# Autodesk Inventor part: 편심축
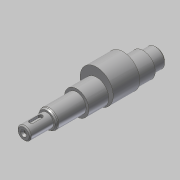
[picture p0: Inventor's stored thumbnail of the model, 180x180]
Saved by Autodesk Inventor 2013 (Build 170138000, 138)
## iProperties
Created: 2019-01
Part Number: 편심축
Material: 강철, 연강
Document SubType Name: Modeling
Designer: mduedu
Density: 7.86 g/cm^3
Mass: 326.79 g
Surface Area: 90.9817 cm^2
Volume: 41.5764 cm^3
Author: mduedu
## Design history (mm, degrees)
sketch "스케치1"
  geometry: L1 (0, 0)-(21, 0); L2 (21, 0)-(21, 6); L3 (21, 6)-(0, 6); L4 (0, 6)-(0, 0); L5 (21, 0)-(48, 0); L6 (48, 0)-(48, 8.5); L7 (48, 8.5)-(21, 8.5); L8 (21, 8.5)-(21, 0); L9 (48, 0)-(108, 0); L10 (108, 0)-(108, 11); L11 (108, 11)-(48, 11); L12 (48, 11)-(48, 0); L13 (108, 0)-(120, 0); L14 (120, 0)-(120, 8.5); L15 (120, 8.5)-(108, 8.5); L16 (108, 8.5)-(108, 0)
  constraints: 32 end point, 8 parallel, 4 horizontal, 4 perpendicular
  dimensions: "d0" = 120 distance between parallel lines of L14 L4; "d2" = 12 distance of L14.end L15.end; "d3" = 60 distance of L10.end L11.end; "d4" = 99 distance between parallel lines of L8 L14; "d5" = 12 diameter of L3 L1; "d6" = 17 diameter of L7 L5; "d7" = 17 diameter of L15 L13; "d8" = 22 diameter of L11 L9
revolve "회전1" sketch "스케치1" stored, may be unused: angle "d9" = 90 deg
node "작업 평면1"
sketch "스케치2"
  geometry: C1 r 15 at (0, 4); C2 r 11 at (0, 0) reference; 1 further point
  constraints: 1 centre point, 1 tangent, 1 vertical alignment
  dimensions: "d11" = 4 distance of point (0, 0) C1.centre
extrude "돌출1" join sketch "스케치2" distance "d12" = 24; taper "d13" = 0 deg
node "작업 평면2"
sketch "스케치3" dims "d16" = 12
  geometry: L1 (-4.5, 2)-(3.5, 2); L2 (3.5, 2)-(3.5, -2); L3 (3.5, -2)-(-4.5, -2); L4 (-4.5, -2)-(-4.5, 2); L5 (-10.5, 8.5)-(-10.5, -8.5) reference; 3 further points
  constraints: 8 end point, 2 midpoint, 2 parallel, 2 vertical alignment, 1 horizontal, 1 horizontal alignment, 1 perpendicular, 4 other
  dimensions: "d14" = 4 distance between parallel lines of L3 L1; "d17" = 4 dimension on L5
extrude "돌출2" cut sketch "스케치3" distance "d18" = 2.5; taper "d19" = 0 deg
chamfer "모따기1" distance "d20" = 1.82; stored, may be unused: second distance "d21" = 2, angle "d22" = 30 deg
fillet "모깎기1" dims "d23" = 2
hole "구멍2" diameter "d39" = 3.242; stored, may be unused: countersink angle "d43" = 60 deg, drill point angle "d45" = 118 deg; dims "d37" = 10, "d38" = 10, "d40" = 8, "d41" = 5.51, "d42" = 2, "d44" = 10
sketch "스케치5"
  geometry: L1 (0, 0)-(2, 0); L2 (2, 0)-(2, 1.621); L3 (0, 2.776)-(0, 0); L4 (0, 2.776)-(2, 1.621); L5 (10, 1.621)-(0, 1.621) reference
  constraints: 8 end point, 1 horizontal, 1 parallel, 1 perpendicular, 1 point on line
  dimensions: "d46" = 2 distance between parallel lines of L2 L3; "d48" = 30 deg angle of L4 L1
revolve "회전2" sketch "스케치5" stored, may be unused: angle "d50" = 90 deg
chamfer "모따기2" distance "d25" = 1; stored, may be unused: second distance "d26" = 2, angle "d27" = 30 deg
node "솔리드1"
